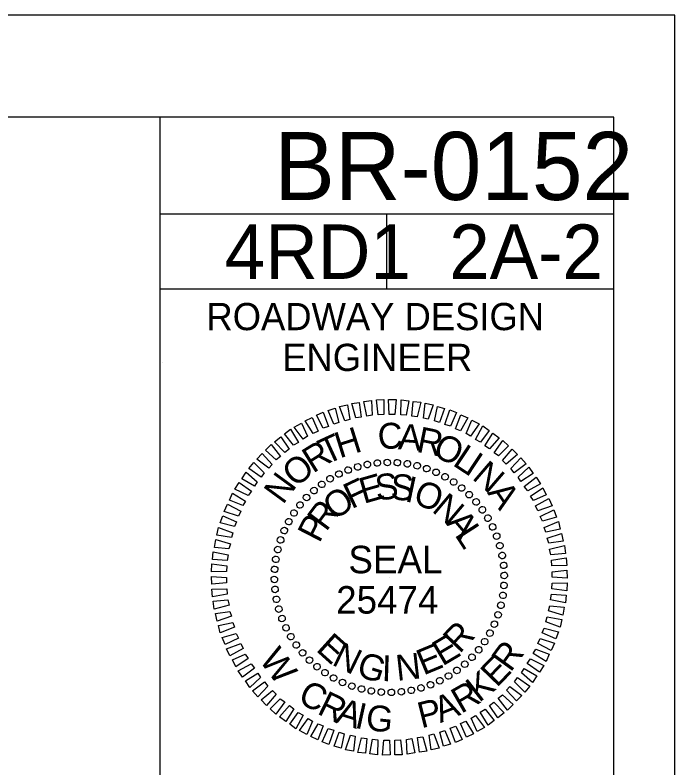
# Model space of a CAD drawing. Extents: x 1553884 to 1554215, y 810431 to 810779.
# Drawn here: x 1554134.52 to 1554156.35, y 810571.05 to 810595.95 of the extents above; entities that cross this region are included whole.
import ezdxf

# ---------------------------------------------------------------- set-up
doc = ezdxf.new("R2010")
doc.units = 0
for name, color, linetype in [('Exist Structure Minor Drop Inlet Top Elevation', 7, 'Continuous'), ('Old_Level_2', 7, 'Continuous'), ('Prop Lane Arrow CELL', 7, 'Continuous'), ('Typical Arrow Superelevation CELL', 7, 'Continuous')]:
    doc.layers.add(name, color=color, linetype=linetype)

msp = doc.modelspace()

# ---------------------------------------------------------------- linework, layer by layer
at = {"layer": 'Exist Structure Minor Drop Inlet Top Elevation'}
for p, q in [((1554139.415, 810584.468), (1554139.415, 810584.468)), ((1554145.853, 810581.017), (1554145.853, 810581.017)), ((1554146.178, 810581.091), (1554146.178, 810581.091)), ((1554146.503, 810581.142), (1554146.503, 810581.142)), ((1554146.837, 810581.163), (1554146.837, 810581.163)), ((1554147.171, 810581.154), (1554147.171, 810581.154)), ((1554147.497, 810581.114), (1554147.497, 810581.114)), ((1554147.824, 810581.052), (1554147.824, 810581.052)), ((1554148.144, 810580.959), (1554148.144, 810580.959)), ((1554145.236, 810580.779), (1554145.236, 810580.779)), ((1554145.537, 810580.913), (1554145.537, 810580.913)), ((1554148.45, 810580.835), (1554148.45, 810580.835)), ((1554148.748, 810580.689), (1554148.748, 810580.689)), ((1554144.943, 810580.622), (1554144.943, 810580.622)), ((1554149.032, 810580.511), (1554149.032, 810580.511)), ((1554144.403, 810580.234), (1554144.403, 810580.234)), ((1554144.665, 810580.435), (1554144.665, 810580.435)), ((1554149.301, 810580.319), (1554149.301, 810580.319)), ((1554144.165, 810580.002), (1554144.165, 810580.002)), ((1554149.547, 810580.096), (1554149.547, 810580.096)), ((1554143.942, 810579.755), (1554143.942, 810579.755)), ((1554149.779, 810579.857), (1554149.779, 810579.857)), ((1554143.749, 810579.486), (1554143.749, 810579.486)), ((1554149.981, 810579.595), (1554149.981, 810579.595)), ((1554143.572, 810579.203), (1554143.572, 810579.203)), ((1554150.168, 810579.318), (1554150.168, 810579.318)), ((1554150.324, 810579.025), (1554150.324, 810579.025)), ((1554143.426, 810578.905), (1554143.426, 810578.905)), ((1554150.459, 810578.724), (1554150.459, 810578.724)), ((1554143.302, 810578.599), (1554143.302, 810578.599)), ((1554143.209, 810578.279), (1554143.209, 810578.279)), ((1554150.563, 810578.407), (1554150.563, 810578.407)), ((1554143.146, 810577.952), (1554143.146, 810577.952)), ((1554150.637, 810578.082), (1554150.637, 810578.082)), ((1554150.688, 810577.757), (1554150.688, 810577.757)), ((1554143.107, 810577.625), (1554143.107, 810577.625)), ((1554143.097, 810577.291), (1554143.097, 810577.291)), ((1554146.903, 810577.358), (1554146.903, 810577.358)), ((1554150.709, 810577.424), (1554150.709, 810577.424)), ((1554143.118, 810576.958), (1554143.118, 810576.958)), ((1554150.699, 810577.09), (1554150.699, 810577.09)), ((1554150.66, 810576.763), (1554150.66, 810576.763)), ((1554143.17, 810576.633), (1554143.17, 810576.633)), ((1554143.243, 810576.308), (1554143.243, 810576.308)), ((1554150.597, 810576.436), (1554150.597, 810576.436)), ((1554143.348, 810575.991), (1554143.348, 810575.991)), ((1554150.504, 810576.116), (1554150.504, 810576.116)), ((1554150.38, 810575.811), (1554150.38, 810575.811)), ((1554143.482, 810575.69), (1554143.482, 810575.69)), ((1554150.234, 810575.512), (1554150.234, 810575.512)), ((1554143.639, 810575.397), (1554143.639, 810575.397)), ((1554150.057, 810575.229), (1554150.057, 810575.229)), ((1554143.825, 810575.12), (1554143.825, 810575.12)), ((1554144.027, 810574.858), (1554144.027, 810574.858)), ((1554149.641, 810574.713), (1554149.641, 810574.713)), ((1554149.865, 810574.96), (1554149.865, 810574.96)), ((1554144.259, 810574.619), (1554144.259, 810574.619)), ((1554149.403, 810574.482), (1554149.403, 810574.482)), ((1554144.505, 810574.396), (1554144.505, 810574.396)), ((1554149.141, 810574.28), (1554149.141, 810574.28)), ((1554144.774, 810574.204), (1554144.774, 810574.204)), ((1554145.058, 810574.027), (1554145.058, 810574.027)), ((1554148.864, 810574.093), (1554148.864, 810574.093)), ((1554145.356, 810573.88), (1554145.356, 810573.88)), ((1554145.662, 810573.756), (1554145.662, 810573.756)), ((1554148.269, 810573.802), (1554148.269, 810573.802)), ((1554148.571, 810573.936), (1554148.571, 810573.936)), ((1554145.982, 810573.663), (1554145.982, 810573.663)), ((1554146.309, 810573.601), (1554146.309, 810573.601)), ((1554146.636, 810573.561), (1554146.636, 810573.561)), ((1554146.969, 810573.552), (1554146.969, 810573.552)), ((1554147.303, 810573.573), (1554147.303, 810573.573)), ((1554147.628, 810573.624), (1554147.628, 810573.624)), ((1554147.953, 810573.698), (1554147.953, 810573.698))]:
    msp.add_line(p, q, dxfattribs=at)
for points in [[(1554146.158, 810582.691), (1554146.058, 810583.167), (1554146.308, 810583.209), (1554146.339, 810582.717)], [(1554146.536, 810582.735), (1554146.475, 810583.227), (1554146.725, 810583.232), (1554146.718, 810582.738)], [(1554146.9, 810582.742), (1554146.876, 810583.234), (1554147.126, 810583.238), (1554147.082, 810582.745)], [(1554147.279, 810582.733), (1554147.293, 810583.226), (1554147.544, 810583.193), (1554147.462, 810582.714)], [(1554145.07, 810582.422), (1554144.881, 810582.873), (1554145.114, 810582.946), (1554145.229, 810582.477)], [(1554145.432, 810582.534), (1554145.257, 810583.009), (1554145.514, 810583.066), (1554145.591, 810582.575)], [(1554145.795, 810582.631), (1554145.658, 810583.107), (1554145.907, 810583.142), (1554145.976, 810582.657)], [(1554147.644, 810582.687), (1554147.696, 810583.173), (1554147.947, 810583.147), (1554147.827, 810582.667)], [(1554148.032, 810582.617), (1554148.092, 810583.111), (1554148.351, 810583.063), (1554148.192, 810582.582)], [(1554148.398, 810582.533), (1554148.496, 810583.005), (1554148.732, 810582.941), (1554148.558, 810582.482)], [(1554144.709, 810582.286), (1554144.496, 810582.723), (1554144.715, 810582.817), (1554144.89, 810582.343)], [(1554148.741, 810582.41), (1554148.899, 810582.89), (1554149.121, 810582.803), (1554148.924, 810582.36)], [(1554149.092, 810582.272), (1554149.266, 810582.73), (1554149.503, 810582.628), (1554149.26, 810582.199)], [(1554144.055, 810581.926), (1554143.76, 810582.323), (1554143.993, 810582.456), (1554144.198, 810582.02)], [(1554144.378, 810582.114), (1554144.121, 810582.534), (1554144.354, 810582.644), (1554144.544, 810582.192)], [(1554149.444, 810582.111), (1554149.633, 810582.554), (1554149.871, 810582.429), (1554149.59, 810582.023)], [(1554143.733, 810581.723), (1554143.438, 810582.097), (1554143.633, 810582.252), (1554143.898, 810581.817)], [(1554149.751, 810581.919), (1554150.001, 810582.364), (1554150.201, 810582.215), (1554149.919, 810581.831)], [(1554143.449, 810581.483), (1554143.109, 810581.841), (1554143.311, 810582.004), (1554143.591, 810581.592)], [(1554150.065, 810581.705), (1554150.331, 810582.127), (1554150.538, 810581.971), (1554150.211, 810581.601)], [(1554143.157, 810581.243), (1554142.81, 810581.563), (1554142.989, 810581.748), (1554143.299, 810581.352)], [(1554150.365, 810581.475), (1554150.661, 810581.882), (1554150.846, 810581.703), (1554150.511, 810581.372)], [(1554142.912, 810580.966), (1554142.52, 810581.262), (1554142.699, 810581.448), (1554143.031, 810581.089)], [(1554150.643, 810581.222), (1554150.962, 810581.592), (1554151.147, 810581.413), (1554150.766, 810581.103)], [(1554150.92, 810580.954), (1554151.255, 810581.309), (1554151.425, 810581.114), (1554151.029, 810580.812)], [(1554142.659, 810580.666), (1554142.252, 810580.954), (1554142.416, 810581.154), (1554142.763, 810580.812)], [(1554151.16, 810580.67), (1554151.518, 810581.002), (1554151.666, 810580.785), (1554151.254, 810580.527)], [(1554142.444, 810580.374), (1554142.023, 810580.617), (1554142.163, 810580.839), (1554142.533, 810580.519)], [(1554142.23, 810580.059), (1554141.794, 810580.271), (1554141.934, 810580.494), (1554142.341, 810580.205)], [(1554151.363, 810580.363), (1554151.759, 810580.665), (1554151.907, 810580.448), (1554151.479, 810580.221)], [(1554151.573, 810580.04), (1554151.985, 810580.32), (1554152.095, 810580.087), (1554151.667, 810579.898)], [(1554142.054, 810579.73), (1554141.618, 810579.904), (1554141.72, 810580.141), (1554142.142, 810579.876)], [(1554151.738, 810579.717), (1554152.174, 810579.96), (1554152.284, 810579.726), (1554151.817, 810579.552)], [(1554141.916, 810579.379), (1554141.443, 810579.537), (1554141.545, 810579.774), (1554141.989, 810579.547)], [(1554151.888, 810579.371), (1554152.339, 810579.583), (1554152.435, 810579.35), (1554151.967, 810579.213)], [(1554141.778, 810579.035), (1554141.305, 810579.156), (1554141.392, 810579.392), (1554141.851, 810579.196)], [(1554152.023, 810579.009), (1554152.498, 810579.199), (1554152.555, 810578.95), (1554152.079, 810578.851)], [(1554141.678, 810578.669), (1554141.199, 810578.752), (1554141.247, 810579.003), (1554141.728, 810578.829)], [(1554152.121, 810578.647), (1554152.596, 810578.807), (1554152.653, 810578.55), (1554152.176, 810578.489)], [(1554141.593, 810578.304), (1554141.115, 810578.348), (1554141.163, 810578.607), (1554141.644, 810578.464)], [(1554141.539, 810577.916), (1554141.054, 810577.946), (1554141.079, 810578.204), (1554141.574, 810578.099)], [(1554152.203, 810578.284), (1554152.694, 810578.407), (1554152.728, 810578.149), (1554152.244, 810578.103)], [(1554152.262, 810577.921), (1554152.754, 810578.006), (1554152.773, 810577.748), (1554152.281, 810577.74)], [(1554141.515, 810577.552), (1554141.023, 810577.543), (1554141.033, 810577.801), (1554141.527, 810577.734)], [(1554152.284, 810577.542), (1554152.776, 810577.589), (1554152.781, 810577.331), (1554152.287, 810577.361)], [(1554141.522, 810577.173), (1554141.03, 810577.126), (1554141.025, 810577.384), (1554141.519, 810577.355)], [(1554141.544, 810576.794), (1554141.052, 810576.709), (1554141.033, 810576.967), (1554141.525, 810576.976)], [(1554152.291, 810577.163), (1554152.783, 810577.172), (1554152.773, 810576.914), (1554152.279, 810576.981)], [(1554152.267, 810576.799), (1554152.753, 810576.769), (1554152.727, 810576.511), (1554152.232, 810576.616)], [(1554141.603, 810576.431), (1554141.112, 810576.308), (1554141.078, 810576.566), (1554141.562, 810576.612)], [(1554141.685, 810576.068), (1554141.21, 810575.908), (1554141.153, 810576.165), (1554141.63, 810576.226)], [(1554152.213, 810576.411), (1554152.691, 810576.367), (1554152.643, 810576.108), (1554152.163, 810576.251)], [(1554152.128, 810576.046), (1554152.607, 810575.963), (1554152.559, 810575.712), (1554152.078, 810575.886)], [(1554141.783, 810575.706), (1554141.308, 810575.516), (1554141.251, 810575.765), (1554141.727, 810575.864)], [(1554141.918, 810575.344), (1554141.467, 810575.132), (1554141.372, 810575.365), (1554141.839, 810575.502)], [(1554152.028, 810575.68), (1554152.501, 810575.559), (1554152.414, 810575.323), (1554151.955, 810575.52)], [(1554151.89, 810575.336), (1554152.363, 810575.178), (1554152.261, 810574.941), (1554151.817, 810575.168)], [(1554142.068, 810574.998), (1554141.632, 810574.755), (1554141.522, 810574.989), (1554141.989, 810575.164)], [(1554151.752, 810574.985), (1554152.188, 810574.811), (1554152.086, 810574.574), (1554151.664, 810574.84)], [(1554142.233, 810574.675), (1554141.821, 810574.395), (1554141.711, 810574.628), (1554142.139, 810574.817)], [(1554142.443, 810574.353), (1554142.047, 810574.05), (1554141.899, 810574.267), (1554142.327, 810574.495)], [(1554151.576, 810574.656), (1554152.012, 810574.444), (1554151.872, 810574.221), (1554151.465, 810574.51)], [(1554151.362, 810574.341), (1554151.783, 810574.098), (1554151.643, 810573.876), (1554151.273, 810574.196)], [(1554142.646, 810574.045), (1554142.288, 810573.713), (1554142.14, 810573.93), (1554142.552, 810574.188)], [(1554151.147, 810574.049), (1554151.554, 810573.761), (1554151.39, 810573.561), (1554151.043, 810573.904)], [(1554142.886, 810573.761), (1554142.551, 810573.406), (1554142.38, 810573.601), (1554142.777, 810573.903)], [(1554150.894, 810573.749), (1554151.286, 810573.453), (1554151.107, 810573.268), (1554150.775, 810573.626)], [(1554143.164, 810573.493), (1554142.844, 810573.123), (1554142.659, 810573.302), (1554143.04, 810573.612)], [(1554150.649, 810573.472), (1554150.996, 810573.152), (1554150.817, 810572.967), (1554150.507, 810573.363)], [(1554143.441, 810573.24), (1554143.145, 810572.833), (1554142.96, 810573.012), (1554143.295, 810573.343)], [(1554150.357, 810573.232), (1554150.697, 810572.874), (1554150.495, 810572.711), (1554150.215, 810573.123)], [(1554143.741, 810573.01), (1554143.475, 810572.588), (1554143.268, 810572.744), (1554143.595, 810573.114)], [(1554150.073, 810572.992), (1554150.368, 810572.618), (1554150.173, 810572.463), (1554149.908, 810572.898)], [(1554144.056, 810572.796), (1554143.805, 810572.351), (1554143.606, 810572.5), (1554143.887, 810572.884)], [(1554149.751, 810572.789), (1554150.046, 810572.392), (1554149.813, 810572.259), (1554149.608, 810572.695)], [(1554144.362, 810572.604), (1554144.173, 810572.161), (1554143.935, 810572.286), (1554144.217, 810572.692)], [(1554144.714, 810572.443), (1554144.54, 810571.985), (1554144.303, 810572.087), (1554144.546, 810572.516)], [(1554149.428, 810572.601), (1554149.685, 810572.181), (1554149.452, 810572.071), (1554149.262, 810572.523)], [(1554145.065, 810572.305), (1554144.907, 810571.825), (1554144.685, 810571.912), (1554144.882, 810572.355)], [(1554145.408, 810572.182), (1554145.311, 810571.71), (1554145.074, 810571.775), (1554145.248, 810572.233)], [(1554148.736, 810572.293), (1554148.925, 810571.842), (1554148.692, 810571.769), (1554148.577, 810572.238)], [(1554149.097, 810572.429), (1554149.31, 810571.993), (1554149.091, 810571.898), (1554148.916, 810572.372)], [(1554145.774, 810572.098), (1554145.714, 810571.604), (1554145.456, 810571.652), (1554145.614, 810572.133)], [(1554146.162, 810572.029), (1554146.11, 810571.542), (1554145.859, 810571.568), (1554145.98, 810572.048)], [(1554146.527, 810571.982), (1554146.513, 810571.489), (1554146.262, 810571.522), (1554146.344, 810572.001)], [(1554147.27, 810571.98), (1554147.331, 810571.488), (1554147.081, 810571.484), (1554147.088, 810571.976)], [(1554147.648, 810572.024), (1554147.748, 810571.548), (1554147.498, 810571.506), (1554147.467, 810571.998)], [(1554148.011, 810572.083), (1554148.148, 810571.608), (1554147.899, 810571.574), (1554147.83, 810572.058)], [(1554148.374, 810572.181), (1554148.549, 810571.706), (1554148.292, 810571.649), (1554148.215, 810572.14)], [(1554146.906, 810571.973), (1554146.93, 810571.481), (1554146.68, 810571.477), (1554146.724, 810571.97)]]:
    msp.add_lwpolyline(points, close=True, dxfattribs=at)
for centre, major_axis in [((1554146.177, 810581.088), (-0.021, 0.107)), ((1554146.505, 810581.137), (-0.011, 0.109)), ((1554146.836, 810581.157), (-0.002, 0.109)), ((1554147.168, 810581.149), (0.008, 0.109)), ((1554147.497, 810581.111), (0.017, 0.108)), ((1554145.54, 810580.905), (-0.039, 0.102)), ((1554145.854, 810581.01), (-0.03, 0.105)), ((1554147.823, 810581.045), (0.026, 0.106)), ((1554148.141, 810580.951), (0.036, 0.103)), ((1554148.449, 810580.829), (0.0444, 0.0997)), ((1554144.944, 810580.615), (-0.0562, 0.0936)), ((1554145.235, 810580.773), (-0.0479, 0.0981)), ((1554148.746, 810580.681), (0.0529, 0.0955)), ((1554144.667, 810580.431), (-0.0642, 0.0883)), ((1554149.029, 810580.508), (0.0611, 0.0905)), ((1554144.407, 810580.225), (-0.0716, 0.0824)), ((1554149.296, 810580.31), (0.0687, 0.0849)), ((1554149.544, 810580.09), (0.0758, 0.0785)), ((1554144.167, 810579.997), (-0.0785, 0.0758)), ((1554149.773, 810579.85), (0.0824, 0.0716)), ((1554143.947, 810579.748), (-0.0849, 0.0687)), ((1554149.979, 810579.59), (0.0883, 0.0642)), ((1554143.749, 810579.481), (-0.0905, 0.0611)), ((1554143.576, 810579.198), (-0.0955, 0.0529)), ((1554150.163, 810579.313), (0.0936, 0.0562)), ((1554143.428, 810578.901), (-0.0997, 0.0444)), ((1554150.321, 810579.022), (0.0981, 0.0479)), ((1554143.306, 810578.593), (-0.103, 0.036)), ((1554150.453, 810578.718), (0.102, 0.039)), ((1554150.558, 810578.403), (0.105, 0.03)), ((1554143.212, 810578.275), (-0.106, 0.026)), ((1554150.636, 810578.08), (0.107, 0.021)), ((1554143.146, 810577.95), (-0.108, 0.017)), ((1554143.108, 810577.62), (-0.109, 0.008)), ((1554150.685, 810577.752), (0.109, 0.011)), ((1554150.705, 810577.421), (0.109, 0.002)), ((1554143.1, 810577.288), (-0.109, -0.002)), ((1554150.697, 810577.089), (0.109, -0.008)), ((1554143.12, 810576.957), (-0.109, -0.011)), ((1554143.169, 810576.629), (-0.107, -0.021)), ((1554150.659, 810576.76), (0.108, -0.017)), ((1554150.593, 810576.434), (0.106, -0.026)), ((1554143.247, 810576.306), (-0.105, -0.03)), ((1554150.499, 810576.116), (0.103, -0.036)), ((1554143.352, 810575.992), (-0.102, -0.039)), ((1554143.484, 810575.687), (-0.0981, -0.0479)), ((1554150.377, 810575.808), (0.0997, -0.0444)), ((1554143.642, 810575.396), (-0.0936, -0.0562)), ((1554150.229, 810575.511), (0.0955, -0.0529)), ((1554143.826, 810575.119), (-0.0883, -0.0642)), ((1554150.056, 810575.228), (0.0905, -0.0611)), ((1554144.032, 810574.859), (-0.0824, -0.0716)), ((1554149.858, 810574.961), (0.0849, -0.0687)), ((1554144.261, 810574.619), (-0.0758, -0.0785)), ((1554149.638, 810574.713), (0.0785, -0.0758)), ((1554144.509, 810574.399), (-0.0687, -0.0849)), ((1554149.398, 810574.484), (0.0716, -0.0824)), ((1554144.776, 810574.201), (-0.0611, -0.0905)), ((1554148.861, 810574.094), (0.0562, -0.0936)), ((1554149.138, 810574.278), (0.0642, -0.0883)), ((1554145.059, 810574.028), (-0.0529, -0.0955)), ((1554145.356, 810573.88), (-0.0444, -0.0997)), ((1554148.57, 810573.936), (0.0479, -0.0981)), ((1554145.664, 810573.758), (-0.036, -0.103)), ((1554145.982, 810573.664), (-0.026, -0.106)), ((1554147.628, 810573.621), (0.021, -0.107)), ((1554147.951, 810573.699), (0.03, -0.105)), ((1554148.265, 810573.804), (0.039, -0.102)), ((1554146.308, 810573.598), (-0.017, -0.108)), ((1554146.637, 810573.561), (-0.008, -0.109)), ((1554146.969, 810573.552), (0.002, -0.109)), ((1554147.3, 810573.572), (0.011, -0.109))]:
    msp.add_ellipse(centre, major_axis=major_axis, ratio=0.999708, dxfattribs=at)
at = {"layer": 'Old_Level_2'}
for p, q in [((1554154.325, 810592.576), (1553906.825, 810592.576)), ((1554139.321, 810434.329), (1554139.325, 810592.576)), ((1554154.321, 810434.329), (1554154.325, 810592.576)), ((1554154.325, 810589.363), (1554139.325, 810589.363)), ((1554146.825, 810586.888), (1554146.825, 810589.363)), ((1554154.325, 810586.888), (1554139.325, 810586.888))]:
    msp.add_line(p, q, dxfattribs=at)
msp.add_circle((1554139.325, 810586.888), 0.009, dxfattribs=at)
at = {"layer": 'Prop Lane Arrow CELL'}
for p, q in [((1554156.35, 810595.951), (1553901.353, 810595.951)), ((1554156.35, 810430.954), (1554156.35, 810595.951))]:
    msp.add_line(p, q, dxfattribs=at)

# ---------------------------------------------------------------- texts
at = {"layer": 'Exist Structure Minor Drop Inlet Top Elevation'}
for s, height, rotation, p in [('C', 0.855, 2.9171, (1554146.539, 810581.588)), ('H', 0.855, 17.4535, (1554145.257, 810581.288)), ('A', 0.855, 355.649, (1554147.177, 810581.593)), ('R', 0.855, 348.3808, (1554147.77, 810581.512)), ('T', 0.855, 24.7216, (1554144.817, 810581.069)), ('O', 0.855, 333.8445, (1554148.29, 810581.404)), ('R', 0.855, 31.9898, (1554144.375, 810580.782)), ('L', 0.855, 326.5763, (1554148.962, 810581.083)), ('I', 0.855, 326.5763, (1554149.348, 810580.828)), ('O', 0.855, 39.2579, (1554143.802, 810580.304)), ('N', 0.855, 319.3082, (1554149.609, 810580.628)), ('N', 0.855, 53.7943, (1554143.385, 810579.736)), ('E', 0.855, 15.9853, (1554146.053, 810579.782)), ('S', 0.855, 6.6414, (1554146.482, 810579.891)), ('S', 0.855, 357.2975, (1554146.935, 810579.924)), ('I', 0.855, 347.9535, (1554147.387, 810579.877)), ('F', 0.855, 25.3292, (1554145.653, 810579.604)), ('O', 0.855, 338.6096, (1554147.647, 810579.821)), ('O', 0.855, 34.6731, (1554145.089, 810579.221)), ('A', 0.855, 304.7718, (1554150.128, 810580.154)), ('N', 0.855, 319.9218, (1554148.277, 810579.553)), ('R', 0.855, 53.361, (1554144.811, 810578.843)), ('A', 0.855, 310.5779, (1554148.757, 810579.135)), ('P', 0.855, 62.7049, (1554144.587, 810578.462)), ('L', 0.855, 302.7465, (1554149.046, 810578.768)), ('SEAL', 0.9096, 0, (1554145.549, 810577.49)), ('25474', 0.9099, 0, (1554145.144, 810576.156)), ('R', 0.855, 46.7271, (1554149.224, 810574.809)), ('E', 0.855, 317.8985, (1554144.446, 810574.946)), ('E', 0.855, 30.5764, (1554148.659, 810574.403)), ('R', 0.855, 54, (1554150.913, 810574.191)), ('W', 0.855, 305.9992, (1554142.575, 810574.629)), ('N', 0.855, 334.0491, (1554144.967, 810574.478)), ('E', 0.855, 22.5011, (1554148.031, 810574.105)), ('G', 0.855, 342.1244, (1554145.776, 810574.11)), ('I', 0.855, 358.2751, (1554146.644, 810573.927)), ('N', 0.855, 6.3504, (1554147.162, 810573.929)), ('E', 0.855, 46, (1554150.456, 810573.687)), ('K', 0.855, 38, (1554149.869, 810573.196)), ('.', 0.855, 310.4999, (1554142.971, 810574.1)), ('C', 0.855, 334, (1554143.836, 810573.229)), ('R', 0.855, 30, (1554149.278, 810572.834)), ('R', 0.855, 334, (1554144.481, 810572.859)), ('A', 0.855, 22, (1554148.591, 810572.533)), ('A', 0.855, 342, (1554145.095, 810572.577)), ('P', 0.855, 14, (1554147.962, 810572.36)), ('I', 0.855, 347.5, (1554145.728, 810572.389)), ('G', 0.855, 354, (1554146.098, 810572.309))]:
    msp.add_text(s, height=height, rotation=rotation, dxfattribs=at).set_placement(p)
at = {"layer": 'Typical Arrow Superelevation CELL'}
for s, height, p in [('BR-0152', 2.25, (1554143.092, 810589.836)), ('4RD1', 1.8, (1554141.461, 810587.226)), ('2A-2', 1.8, (1554148.884, 810587.226)), ('ROADWAY DESIGN', 0.9, (1554140.853, 810585.53)), ('ENGINEER', 0.9, (1554143.36, 810584.18))]:
    msp.add_text(s, height=height, dxfattribs=at).set_placement(p)

doc.saveas('drawing.dxf')
